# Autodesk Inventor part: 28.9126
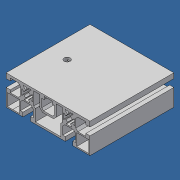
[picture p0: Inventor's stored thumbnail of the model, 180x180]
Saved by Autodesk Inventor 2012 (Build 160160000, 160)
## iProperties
Created: 2007-06
Part Number: 28.9126
Material: Aluminum-6061
Document SubType Name: Modeling
Designer: Andy Moles
Density: 2.71 g/cm^3
Description: L = 3.543", MILL TO 28.9126
Stock Number: 20.1066 PROFILE 90X32
Vendor: F
Mass: 225.941 g
Surface Area: 767.943 cm^2
Volume: 83.3729 cm^3
Author: Andy Moles
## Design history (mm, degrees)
sketch "Sketch1"
  geometry: L1 (4.25, 7.901)-(4.25, 5) reference; L2 (6.8, 5)-(6.8, -3.8) reference; L3 (6.8, -3.8)-(4.8, -5.8) reference; L4 (4.8, -5.8)-(-4.8, -5.8) reference; L5 (-4.8, -5.8)-(-6.8, -3.8) reference; L6 (-6.8, -3.8)-(-6.8, 5) reference; L7 (-4.25, 5)-(-4.25, 7.901) reference; L8 (-45, 9.5)-(45, 9.5) reference; L9 (-45, 4.1)-(-40.5, 4.1) reference; L10 (-40.5, 6.8)-(-32, 6.8) reference; L11 (-32, 6.8)-(-29.7, 4.5) reference; L12 (-29.7, 4.5)-(-29.7, -4.5) reference; L13 (-29.7, -4.5)-(-32, -6.8) reference; L14 (-32, -6.8)-(-40.5, -6.8) reference; L15 (-40.5, -4.1)-(-45, -4.1) reference; L16 (-45, -22.5)-(-45, -4.4) reference; L17 (45, -4.1)-(40.5, -4.1) reference; L18 (40.5, -6.8)-(32, -6.8) reference; L19 (32, -6.8)-(29.7, -4.5) reference; L20 (29.7, -4.5)-(29.7, 4.5) reference; L21 (29.7, 4.5)-(32, 6.8) reference; L22 (32, 6.8)-(40.5, 6.8) reference; L23 (40.5, 4.1)-(45, 4.1) reference; L24 (-43.6, -21.1)-(-43.6, -8.2) reference; L25 (-43.6, -13.915)-(-43.6, -9.2) reference; L26 (-43.6, -8.2)-(-36.415, -8.2) reference; L27 (-36.415, -8.2)-(-30.7, -8.2) reference; L28 (-30.7, -8.2)-(-30.7, -21.1) reference; L29 (-30.7, -21.1)-(-37.885, -21.1) reference; L30 (-37.885, -21.1)-(-43.6, -21.1) reference; L31 (30.7, -21.1)-(30.7, -8.2) reference; L32 (30.7, -8.2)-(43.6, -8.2) reference; L33 (43.6, -8.2)-(43.6, -21.1) reference; L34 (43.6, -21.1)-(30.7, -21.1) reference; L35 (-28.3, -2.813)-(-28.3, 2.813) reference; L36 (-27.788, 3.025)-(-26.269, 1.506) reference; L37 (-24.006, 3.769)-(-26.725, 6.488) reference; L38 (-26.513, 7)-(-23.753, 7) reference; L39 (-23.464, 6.778)-(-23.08, 5.345) reference; L40 (-21.92, 5.345)-(-21.536, 6.778) reference; L41 (-21.247, 7)-(-18.487, 7) reference; L42 (-18.275, 6.488)-(-20.994, 3.769) reference; L43 (-18.731, 1.506)-(-17.212, 3.025) reference; L44 (-16.7, 2.813)-(-16.7, -2.813) reference; L45 (-17.212, -3.025)-(-18.731, -1.506) reference; L46 (-20.994, -3.769)-(-19.475, -5.288) reference; L47 (-19.687, -5.8)-(-25.313, -5.8) reference; L48 (-25.525, -5.288)-(-24.006, -3.769) reference; L49 (-26.269, -1.506)-(-27.788, -3.025) reference; L50 (16.7, -2.813)-(16.7, 2.813) reference; L51 (17.212, 3.025)-(18.731, 1.506) reference; L52 (20.994, 3.769)-(18.275, 6.488) reference; L53 (18.487, 7)-(21.247, 7) reference; L54 (21.536, 6.778)-(21.92, 5.345) reference; L55 (23.08, 5.345)-(23.464, 6.778) reference; L56 (23.753, 7)-(26.513, 7) reference; L57 (26.725, 6.488)-(24.006, 3.769) reference; L58 (26.269, 1.506)-(27.788, 3.025) reference; L59 (28.3, 2.813)-(28.3, -2.813) reference; L60 (27.788, -3.025)-(26.269, -1.506) reference; L61 (24.006, -3.769)-(25.525, -5.288) reference; L62 (25.313, -5.8)-(19.687, -5.8) reference; L63 (19.475, -5.288)-(20.994, -3.769) reference; L64 (18.731, -1.506)-(17.212, -3.025) reference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; A1 r 0.3 centre (-28, 2.813) between (-27.788, 3.025) and (-28.3, 2.813) reference; A2 r 0.3 centre (-26.057, 1.718) between (-26.269, 1.506) and (-25.787, 1.588) reference; A3 r 3.65 centre (-22.5, 0) between (-24.088, 3.287) and (-25.787, 1.588) reference; A4 r 0.3 centre (-24.218, 3.557) between (-24.088, 3.287) and (-24.006, 3.769) reference; A5 r 0.3 centre (-26.513, 6.7) between (-26.513, 7) and (-26.725, 6.488) reference; A6 r 0.3 centre (-23.753, 6.7) between (-23.464, 6.778) and (-23.753, 7) reference; A7 r 0.6 centre (-22.5, 5.5) between (-23.08, 5.345) and (-21.92, 5.345) reference; A8 r 0.3 centre (-21.247, 6.7) between (-21.247, 7) and (-21.536, 6.778) reference; A9 r 0.3 centre (-18.487, 6.7) between (-18.275, 6.488) and (-18.487, 7) reference; A10 r 0.3 centre (-20.782, 3.557) between (-20.994, 3.769) and (-20.912, 3.287) reference; A11 r 3.65 centre (-22.5, 0) between (-19.213, 1.588) and (-20.912, 3.287) reference; A12 r 0.3 centre (-18.943, 1.718) between (-19.213, 1.588) and (-18.731, 1.506) reference; A13 r 0.3 centre (-17, 2.813) between (-16.7, 2.813) and (-17.212, 3.025) reference; A14 r 0.3 centre (-17, -2.813) between (-17.212, -3.025) and (-16.7, -2.813) reference; A15 r 0.3 centre (-18.943, -1.718) between (-18.731, -1.506) and (-19.213, -1.588) reference; A16 r 3.65 centre (-22.5, 0) between (-20.912, -3.287) and (-19.213, -1.588) reference; A17 r 0.3 centre (-20.782, -3.557) between (-20.912, -3.287) and (-20.994, -3.769) reference; A18 r 0.3 centre (-19.687, -5.5) between (-19.687, -5.8) and (-19.475, -5.288) reference; A19 r 0.3 centre (-25.313, -5.5) between (-25.525, -5.288) and (-25.313, -5.8) reference; A20 r 0.3 centre (-24.218, -3.557) between (-24.006, -3.769) and (-24.088, -3.287) reference; A21 r 3.65 centre (-22.5, 0) between (-25.787, -1.588) and (-24.088, -3.287) reference; A22 r 0.3 centre (-26.057, -1.718) between (-25.787, -1.588) and (-26.269, -1.506) reference; A23 r 0.3 centre (-28, -2.813) between (-28.3, -2.813) and (-27.788, -3.025) reference; A24 r 0.3 centre (17, 2.813) between (17.212, 3.025) and (16.7, 2.813) reference; A25 r 0.3 centre (18.943, 1.718) between (18.731, 1.506) and (19.213, 1.588) reference; A26 r 3.65 centre (22.5, 0) between (20.912, 3.287) and (19.213, 1.588) reference; A27 r 0.3 centre (20.782, 3.557) between (20.912, 3.287) and (20.994, 3.769) reference; A28 r 0.3 centre (18.487, 6.7) between (18.487, 7) and (18.275, 6.488) reference; A29 r 0.3 centre (21.247, 6.7) between (21.536, 6.778) and (21.247, 7) reference; A30 r 0.6 centre (22.5, 5.5) between (21.92, 5.345) and (23.08, 5.345) reference; A31 r 0.3 centre (23.753, 6.7) between (23.753, 7) and (23.464, 6.778) reference; A32 r 0.3 centre (26.513, 6.7) between (26.725, 6.488) and (26.513, 7) reference; A33 r 0.3 centre (24.218, 3.557) between (24.006, 3.769) and (24.088, 3.287) reference; A34 r 3.65 centre (22.5, 0) between (25.787, 1.588) and (24.088, 3.287) reference; A35 r 0.3 centre (26.057, 1.718) between (25.787, 1.588) and (26.269, 1.506) reference; A36 r 0.3 centre (28, 2.813) between (28.3, 2.813) and (27.788, 3.025) reference; A37 r 0.3 centre (28, -2.813) between (27.788, -3.025) and (28.3, -2.813) reference; A38 r 0.3 centre (26.057, -1.718) between (26.269, -1.506) and (25.787, -1.588) reference; A39 r 3.65 centre (22.5, 0) between (24.088, -3.287) and (25.787, -1.588) reference; A40 r 0.3 centre (24.218, -3.557) between (24.088, -3.287) and (24.006, -3.769) reference; A41 r 0.3 centre (25.313, -5.5) between (25.313, -5.8) and (25.525, -5.288) reference; A42 r 0.3 centre (19.687, -5.5) between (19.475, -5.288) and (19.687, -5.8) reference; A43 r 0.3 centre (20.782, -3.557) between (20.994, -3.769) and (20.912, -3.287) reference; A44 r 3.65 centre (22.5, 0) between (19.213, -1.588) and (20.912, -3.287) reference; A45 r 0.3 centre (18.943, -1.718) between (19.213, -1.588) and (18.731, -1.506) reference; A46 r 0.3 centre (17, -2.813) between (16.7, -2.813) and (17.212, -3.025) reference
  constraints: 226 end point, 92 point on circle, 46 centre point, 31 horizontal, 24 vertical, 3 point on line, 1 perpendicular, 309 other
extrude "Extrusion1" new body sketch "Sketch1" stored distance "d18" = 90; taper "d19" = 0 deg
hole "Hole1" diameter "d22" = 6.5; stored, may be unused: countersink angle "d26" = 90 deg, drill point angle "d28" = 118 deg; dims "d20" = 45, "d21" = 20.5, "d23" = 6, "d24" = 4, "d25" = 2, "d27" = 8
body "Solid1"
other parameters: "d14" = 32
